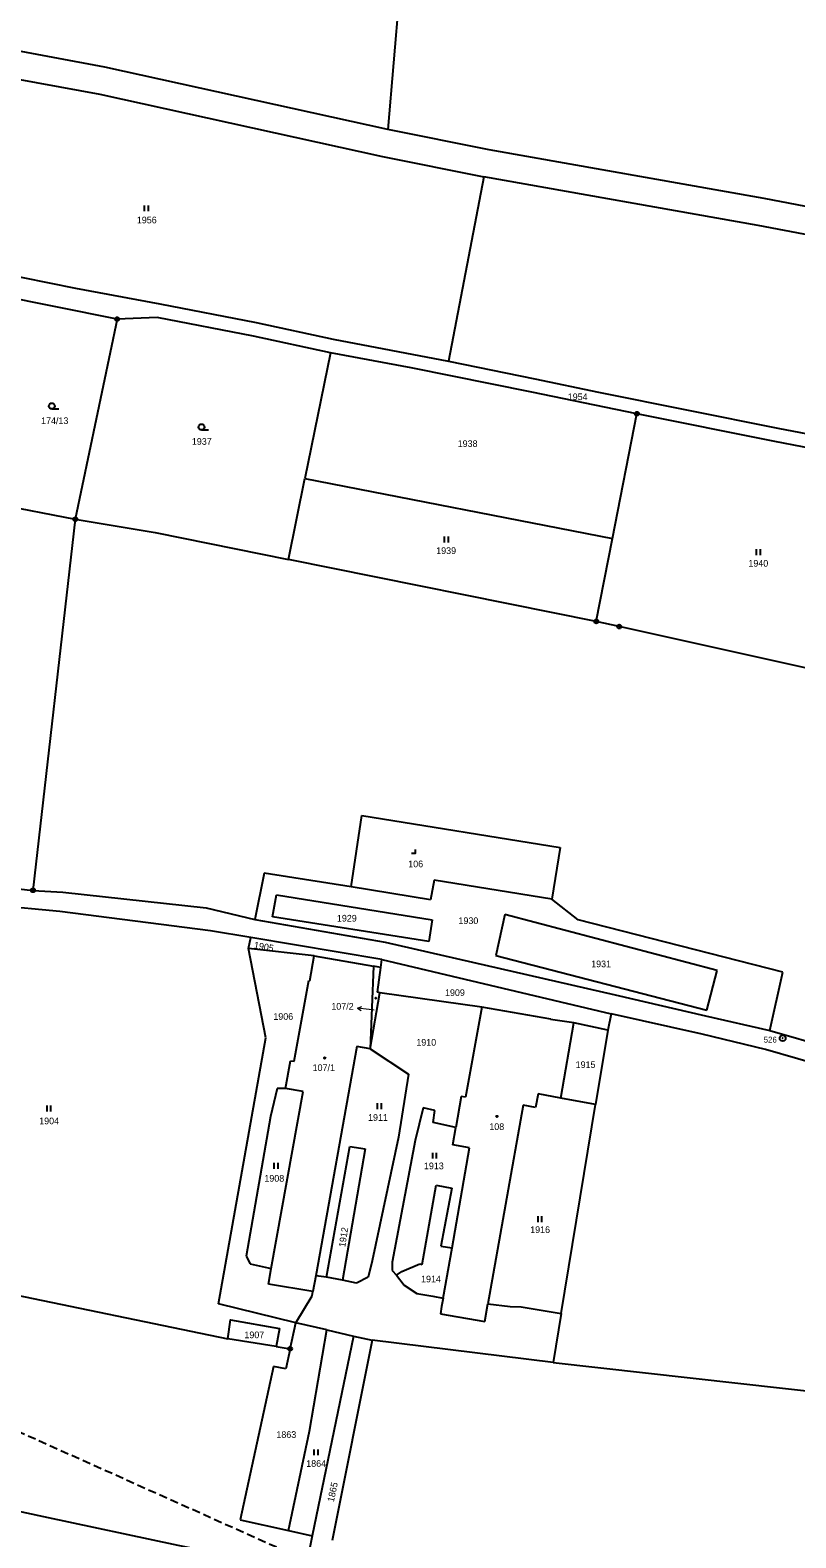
# Model space of a CAD drawing. Extents: x -601131 to -597152, y -1058536 to -1055911.
# Drawn here: x -599237.3 to -599042.1, y -1056861.6 to -1056477.3 of the extents above; entities that cross this region are included whole.
import ezdxf
from ezdxf.enums import TextEntityAlignment as Align

# ---------------------------------------------------------------- set-up
doc = ezdxf.new("R2010")
doc.units = 0
doc.header["$LTSCALE"] = 0.68
doc.linetypes.add('MEDIUM_DASHED', pattern=[4.5, 3, -1.5])
for name, color, linetype, lineweight in [('1', 7, 'Continuous', 25), ('3', 7, 'Continuous', 25), ('5', 7, 'Continuous', 25), ('6', 7, 'Continuous', 25), ('7', 7, 'Continuous', 13), ('8', 7, 'Continuous', 25)]:
    doc.layers.add(name, color=color, linetype=linetype, lineweight=lineweight)
doc.layers.add('2', color=7, linetype='Continuous')

msp = doc.modelspace()

# ---------------------------------------------------------------- linework, layer by layer
at = {"layer": '1'}
for p, q in [((-599138.92, -1056418.42), (-599146.08, -1056502.65)), ((-599218.22, -1056486.75), (-599246.19, -1056481.54)), ((-599249.34, -1056488.19), (-599219.47, -1056493.64)), ((-599146.08, -1056502.65), (-599218.22, -1056486.75)), ((-599219.47, -1056493.64), (-599147.48, -1056509.51)), ((-599120.3, -1056507.82), (-599146.08, -1056502.65)), ((-599050.18, -1056520.28), (-599120.3, -1056507.82)), ((-599147.48, -1056509.51), (-599121.64, -1056514.69)), ((-599121.64, -1056514.69), (-599130.68, -1056561.74)), ((-599051.76, -1056527.1), (-599121.64, -1056514.69)), ((-598999.34, -1056530.04), (-599050.18, -1056520.28)), ((-599000.76, -1056536.89), (-599051.76, -1056527.1)), ((-599254.19, -1056537.36), (-599225.68, -1056543.1)), ((-599215.08, -1056551), (-599254.26, -1056543.1)), ((-599225.68, -1056543.1), (-599204.19, -1056547.14)), ((-599204.19, -1056547.14), (-599179.64, -1056551.87)), ((-599215.08, -1056551), (-599225.75, -1056602)), ((-599204.88, -1056550.57), (-599215.08, -1056551)), ((-599180.34, -1056555.3), (-599204.88, -1056550.57)), ((-599179.64, -1056551.87), (-599160.02, -1056556.11)), ((-599160.69, -1056559.55), (-599180.34, -1056555.3)), ((-599160.02, -1056556.11), (-599130.68, -1056561.74)), ((-599160.69, -1056559.55), (-599167.22, -1056591.58)), ((-599140.17, -1056563.39), (-599160.69, -1056559.55)), ((-599130.68, -1056561.74), (-599108.66, -1056566.19)), ((-599109.4, -1056569.61), (-599140.17, -1056563.39)), ((-599108.66, -1056566.19), (-599092.43, -1056569.59)), ((-599082.63, -1056575.11), (-599109.4, -1056569.61)), ((-599092.43, -1056569.59), (-599046.74, -1056578.78)), ((-599088.85, -1056606.91), (-599082.63, -1056575.11)), ((-599047.5, -1056582.19), (-599082.63, -1056575.11)), ((-599046.74, -1056578.78), (-599000.52, -1056587.59)), ((-599001.09, -1056591.04), (-599047.5, -1056582.19)), ((-599171.43, -1056612.23), (-599167.22, -1056591.58)), ((-599167.22, -1056591.58), (-599088.85, -1056606.91)), ((-599265.11, -1056594.43), (-599225.75, -1056602)), ((-599225.75, -1056602), (-599236.54, -1056696.59)), ((-599225.75, -1056602), (-599205.44, -1056605.38)), ((-599205.44, -1056605.38), (-599171.43, -1056612.23)), ((-599092.98, -1056628.05), (-599088.85, -1056606.91)), ((-599092.98, -1056628.05), (-599171.43, -1056612.23)), ((-599087.13, -1056629.35), (-599092.98, -1056628.05)), ((-599039.03, -1056640.06), (-599087.13, -1056629.35)), ((-599155.42, -1056695.72), (-599152.74, -1056677.55)), ((-599152.74, -1056677.55), (-599102.17, -1056685.67)), ((-599102.17, -1056685.67), (-599104.32, -1056698.83)), ((-599177.64, -1056692.2), (-599179.99, -1056704.03)), ((-599155.42, -1056695.72), (-599177.64, -1056692.2)), ((-599257.46, -1056694.29), (-599236.54, -1056696.59)), ((-599135.22, -1056698.99), (-599155.42, -1056695.72)), ((-599134.28, -1056694.02), (-599135.22, -1056698.99)), ((-599104.32, -1056698.83), (-599134.28, -1056694.02)), ((-599229.72, -1056702.02), (-599261.35, -1056698.89)), ((-599236.54, -1056696.59), (-599228.94, -1056697.02)), ((-599228.94, -1056697.02), (-599192.37, -1056701.08)), ((-599175.52, -1056703.3), (-599174.47, -1056697.69)), ((-599174.47, -1056697.69), (-599134.79, -1056704.07)), ((-599097.57, -1056704.11), (-599104.32, -1056698.83)), ((-599191.33, -1056706.93), (-599229.72, -1056702.02)), ((-599192.37, -1056701.08), (-599179.99, -1056704.03)), ((-599135.66, -1056709.64), (-599175.52, -1056703.3)), ((-599116.27, -1056702.75), (-599118.62, -1056713.23)), ((-599062.17, -1056716.98), (-599116.27, -1056702.75)), ((-599181.05, -1056708.63), (-599191.33, -1056706.93)), ((-599179.99, -1056704.03), (-599146.83, -1056709.8)), ((-599134.79, -1056704.07), (-599135.66, -1056709.64)), ((-599045.45, -1056717.46), (-599097.57, -1056704.11)), ((-599181.64, -1056711.41), (-599181.05, -1056708.63)), ((-599164.91, -1056713.29), (-599181.64, -1056711.41)), ((-599177.22, -1056734.19), (-599181.64, -1056711.41)), ((-599147.65, -1056714.22), (-599181.05, -1056708.63)), ((-599146.83, -1056709.8), (-599088.14, -1056723.22)), ((-599165.97, -1056719.61), (-599164.91, -1056713.29)), ((-599164.91, -1056713.29), (-599149.77, -1056715.9)), ((-599147.86, -1056716.23), (-599147.65, -1056714.22)), ((-599147.65, -1056714.22), (-599089.21, -1056728.1)), ((-599118.62, -1056713.23), (-599064.81, -1056727.13)), ((-599149.77, -1056715.9), (-599150.65, -1056736.94)), ((-599147.86, -1056716.23), (-599149.77, -1056715.9)), ((-599148.73, -1056722.58), (-599147.86, -1056716.23)), ((-599064.81, -1056727.13), (-599062.17, -1056716.98)), ((-599048.72, -1056732.31), (-599045.45, -1056717.46)), ((-599169.99, -1056740.15), (-599166.23, -1056719.58)), ((-599166.23, -1056719.58), (-599165.97, -1056719.61)), ((-599150.65, -1056736.94), (-599148.12, -1056722.73)), ((-599148.12, -1056722.73), (-599148.73, -1056722.58)), ((-599122.18, -1056726.39), (-599148.12, -1056722.73)), ((-599122.18, -1056726.39), (-599126.28, -1056749.34)), ((-599104.59, -1056729.38), (-599122.18, -1056726.39)), ((-599088.14, -1056723.22), (-599065.18, -1056728.58)), ((-599104.63, -1056729.5), (-599104.59, -1056729.38)), ((-599098.69, -1056730.39), (-599104.63, -1056729.5)), ((-599102.04, -1056749.55), (-599098.69, -1056730.39)), ((-599090.02, -1056732.25), (-599098.69, -1056730.39)), ((-599089.21, -1056728.1), (-599090.02, -1056732.25)), ((-599066.02, -1056733.24), (-599089.21, -1056728.1)), ((-599065.18, -1056728.58), (-599048.72, -1056732.31)), ((-599189.28, -1056801.96), (-599177.22, -1056734.19)), ((-599090.02, -1056732.25), (-599093.15, -1056751.21)), ((-599049.89, -1056737.17), (-599066.02, -1056733.24)), ((-599048.72, -1056732.31), (-599011.59, -1056742.97)), ((-599154.04, -1056736.41), (-599164.49, -1056794.86)), ((-599150.65, -1056736.94), (-599154.04, -1056736.41)), ((-599150.65, -1056736.94), (-599140.87, -1056743.46)), ((-599012.96, -1056747.77), (-599049.89, -1056737.17)), ((-599172.18, -1056747.08), (-599170.92, -1056740.04)), ((-599170.92, -1056740.04), (-599169.99, -1056740.15)), ((-599140.87, -1056743.46), (-599143.41, -1056759.46)), ((-599174.33, -1056747.05), (-599175.97, -1056754.24)), ((-599175.82, -1056792.93), (-599167.72, -1056747.89)), ((-599172.18, -1056747.08), (-599174.33, -1056747.05)), ((-599167.72, -1056747.89), (-599172.18, -1056747.08)), ((-599127.43, -1056749.17), (-599128.81, -1056757.02)), ((-599126.28, -1056749.34), (-599127.43, -1056749.17)), ((-599107.83, -1056748.49), (-599108.45, -1056751.91)), ((-599102.04, -1056749.55), (-599107.83, -1056748.49)), ((-599093.15, -1056751.21), (-599102.04, -1056749.55)), ((-599137.14, -1056752.04), (-599139.17, -1056760.36)), ((-599134.12, -1056752.73), (-599137.14, -1056752.04)), ((-599134.56, -1056755.73), (-599134.12, -1056752.73)), ((-599111.64, -1056751.38), (-599120.61, -1056801.94)), ((-599108.45, -1056751.91), (-599111.64, -1056751.38)), ((-599101.95, -1056804.44), (-599093.15, -1056751.21)), ((-599175.97, -1056754.24), (-599182.25, -1056789.79)), ((-599128.81, -1056757.02), (-599134.56, -1056755.73)), ((-599129.58, -1056761.41), (-599128.81, -1056757.02)), ((-599143.41, -1056759.46), (-599150.12, -1056790.98)), ((-599139.17, -1056760.36), (-599145.03, -1056791.37)), ((-599125.26, -1056762.22), (-599129.58, -1056761.41)), ((-599161.71, -1056795.16), (-599155.82, -1056761.88)), ((-599151.87, -1056762.51), (-599157.68, -1056795.91)), ((-599155.82, -1056761.88), (-599151.87, -1056762.51)), ((-599129.75, -1056787.69), (-599125.26, -1056762.22)), ((-599137.36, -1056791.91), (-599133.78, -1056771.74)), ((-599133.78, -1056771.74), (-599129.84, -1056772.46)), ((-599129.84, -1056772.46), (-599132.6, -1056787.28)), ((-599132.6, -1056787.28), (-599129.75, -1056787.69)), ((-599132.01, -1056800.51), (-599129.75, -1056787.69)), ((-599289.36, -1056789.62), (-599186.88, -1056810.87)), ((-599182.25, -1056789.79), (-599181.15, -1056791.8)), ((-599181.15, -1056791.8), (-599175.82, -1056792.93)), ((-599150.12, -1056790.98), (-599151.08, -1056795.18)), ((-599145.03, -1056791.37), (-599145.01, -1056793.47)), ((-599142.57, -1056793.75), (-599137.95, -1056791.8)), ((-599137.95, -1056791.8), (-599137.36, -1056791.91)), ((-599176.55, -1056796.94), (-599175.82, -1056792.93)), ((-599164.49, -1056794.86), (-599165.21, -1056798.87)), ((-599161.71, -1056795.16), (-599164.49, -1056794.86)), ((-599157.68, -1056795.91), (-599161.71, -1056795.16)), ((-599154.07, -1056796.68), (-599157.68, -1056795.91)), ((-599151.08, -1056795.18), (-599154.07, -1056796.68)), ((-599145.01, -1056793.47), (-599143.93, -1056794.63)), ((-599143.93, -1056794.63), (-599142.57, -1056793.75)), ((-599143.93, -1056794.63), (-599141.97, -1056797.21)), ((-599165.21, -1056798.87), (-599176.55, -1056796.94)), ((-599169.54, -1056806.85), (-599165.39, -1056799.96)), ((-599165.39, -1056799.96), (-599165.21, -1056798.87)), ((-599141.97, -1056797.21), (-599138.73, -1056799.35)), ((-599138.73, -1056799.35), (-599134.62, -1056800.05)), ((-599169.54, -1056806.85), (-599189.28, -1056801.96)), ((-599134.62, -1056800.05), (-599132.01, -1056800.51)), ((-599132.39, -1056802.68), (-599132.72, -1056804.55)), ((-599132.01, -1056800.51), (-599132.39, -1056802.68)), ((-599121.41, -1056806.45), (-599120.61, -1056801.94)), ((-599120.61, -1056801.94), (-599114.91, -1056802.66)), ((-599114.91, -1056802.66), (-599112.1, -1056802.76)), ((-599112.1, -1056802.76), (-599101.95, -1056804.44)), ((-599171.01, -1056813.42), (-599169.54, -1056806.85)), ((-599161.69, -1056808.64), (-599169.54, -1056806.85)), ((-599132.72, -1056804.55), (-599121.41, -1056806.45)), ((-599101.95, -1056804.44), (-599104.01, -1056816.89)), ((-599174.53, -1056812.86), (-599186.88, -1056810.87)), ((-599173.72, -1056808.24), (-599174.53, -1056812.86)), ((-599166.08, -1056834.46), (-599161.69, -1056808.64)), ((-599154.89, -1056810.19), (-599165.35, -1056861.13)), ((-599161.69, -1056808.64), (-599154.89, -1056810.19)), ((-599150.14, -1056811.27), (-599160.28, -1056862.26)), ((-599154.89, -1056810.19), (-599150.14, -1056811.27)), ((-599104.01, -1056816.89), (-599150.14, -1056811.27)), ((-599174.53, -1056812.86), (-599171.01, -1056813.42)), ((-599171.01, -1056813.42), (-599172.14, -1056818.5)), ((-599175.28, -1056817.96), (-599183.76, -1056857.04)), ((-599172.14, -1056818.5), (-599175.28, -1056817.96)), ((-599104.01, -1056816.89), (-598929.16, -1056836.6)), ((-599171.43, -1056859.78), (-599166.08, -1056834.46)), ((-599233.79, -1056856.28), (-599243.65, -1056854.14)), ((-599183.76, -1056857.04), (-599171.43, -1056859.78)), ((-599171.43, -1056859.78), (-599165.35, -1056861.13)), ((-599165.35, -1056861.13), (-599167.19, -1056870.09))]:
    msp.add_line(p, q, dxfattribs=at)
for points in [[(-599186.88, -1056810.87), (-599186.2, -1056806.05), (-599173.72, -1056808.24)], [(-599178.14, -1056867.87), (-599199.51, -1056863.54), (-599233.79, -1056856.28)]]:
    msp.add_lwpolyline(points, dxfattribs=at)
at = {"layer": '3'}
for p, q in [((-599208.131, -1056523.5), (-599208.131, -1056522)), ((-599207.13, -1056523.5), (-599207.13, -1056522)), ((-599231.723, -1056573.89), (-599229.973, -1056573.89)), ((-599193.593, -1056579.25), (-599191.843, -1056579.25)), ((-599131.681, -1056607.89), (-599131.681, -1056606.39)), ((-599130.68, -1056607.89), (-599130.68, -1056606.39)), ((-599052.161, -1056611.17), (-599052.161, -1056609.67)), ((-599051.16, -1056611.17), (-599051.16, -1056609.67)), ((-599232.951, -1056752.92), (-599232.951, -1056751.42)), ((-599231.95, -1056752.92), (-599231.95, -1056751.42)), ((-599148.751, -1056752.35), (-599148.751, -1056750.85)), ((-599147.75, -1056752.35), (-599147.75, -1056750.85)), ((-599134.671, -1056764.97), (-599134.671, -1056763.47)), ((-599133.67, -1056764.97), (-599133.67, -1056763.47)), ((-599175.041, -1056767.56), (-599175.041, -1056766.06)), ((-599174.04, -1056767.56), (-599174.04, -1056766.06)), ((-599107.831, -1056781.12), (-599107.831, -1056779.62)), ((-599106.83, -1056781.12), (-599106.83, -1056779.62)), ((-599164.891, -1056840.58), (-599164.891, -1056839.08)), ((-599163.89, -1056840.58), (-599163.89, -1056839.08))]:
    msp.add_line(p, q, dxfattribs=at)
msp.add_lwpolyline([(-599140.051, -1056687.15), (-599139.05, -1056687.15), (-599139.05, -1056686.15)], dxfattribs=at)
for centre in [(-599231.7229, -1056573.1398), (-599193.5929, -1056578.4998)]:
    msp.add_circle(centre, 0.75, dxfattribs=at)
at = {"layer": '5'}
for centre in [(-599149.1668, -1056724.0692), (-599162.1768, -1056739.3192), (-599118.3168, -1056754.2092)]:
    msp.add_circle(centre, 0.175, dxfattribs=at)
at = {"layer": '6', "linetype": 'MEDIUM_DASHED'}
msp.add_line((-599168.92, -1056866.53), (-599311.59, -1056802.59), dxfattribs=at)
at = {"layer": '7'}
msp.add_line((-599153.819, -1056726.574), (-599152.886, -1056727.193), dxfattribs=at)
msp.add_lwpolyline([(-599149.6, -1056727.09), (-599150.84, -1056726.94), (-599153.819, -1056726.574), (-599152.764, -1056726.199)], dxfattribs=at)
at = {"layer": '8'}
for centre, radius in [((-599215.08, -1056550.9999), 0.5), ((-599215.08, -1056550.9999), 0.0303), ((-599082.63, -1056575.1099), 0.5), ((-599082.63, -1056575.1099), 0.0303), ((-599225.75, -1056601.9999), 0.5), ((-599225.75, -1056601.9999), 0.0303), ((-599092.98, -1056628.0499), 0.5), ((-599092.98, -1056628.0499), 0.0303), ((-599087.13, -1056629.3499), 0.5), ((-599087.13, -1056629.3499), 0.0303), ((-599236.54, -1056696.5899), 0.5), ((-599236.54, -1056696.5899), 0.0303), ((-599045.48, -1056734.2698), 0.75), ((-599045.48, -1056734.2698), 0.03), ((-599171.01, -1056813.4199), 0.5), ((-599171.01, -1056813.4199), 0.0303)]:
    msp.add_circle(centre, radius, dxfattribs=at)

# ---------------------------------------------------------------- texts
at = {"layer": '2'}
for s, p in [('1956', (-599207.54, -1056526.582)), ('1954', (-599097.73, -1056571.642)), ('1937', (-599193.52, -1056583.022)), ('1938', (-599125.78, -1056583.582)), ('1939', (-599131.25, -1056610.852)), ('1940', (-599051.69, -1056614.082)), ('106', (-599139.009, -1056690.702)), ('1929', (-599156.56, -1056704.542)), ('1930', (-599125.58, -1056705.172)), ('1931', (-599091.76, -1056716.182)), ('1909', (-599129.01, -1056723.502)), ('1906', (-599172.76, -1056729.592)), ('1910', (-599136.32, -1056736.172)), ('107/1', (-599162.43, -1056742.652)), ('1915', (-599095.72, -1056741.862)), ('1911', (-599148.62, -1056755.332)), ('1904', (-599232.43, -1056756.202)), ('108', (-599118.349, -1056757.662)), ('1908', (-599175.04, -1056770.842)), ('1913', (-599134.38, -1056767.662)), ('1916', (-599107.3, -1056783.932)), ('1914', (-599135.11, -1056796.502)), ('1907', (-599180.13, -1056810.732)), ('1863', (-599171.98, -1056836.142)), ('1864', (-599164.37, -1056843.522))]:
    msp.add_text(s, height=1.7, dxfattribs=at).set_placement(p, align=Align.CENTER)
msp.add_text('174/13', height=1.7, dxfattribs=at).set_placement((-599234.47, -1056577.745))
for s, rotation, p in [('1905', 350, (-599177.8366, -1056711.7761)), ('1912', 81, (-599156.5818, -1056785.122)), ('1865', 78, (-599159.3556, -1056850.1157))]:
    msp.add_text(s, height=1.7, rotation=rotation, dxfattribs=at).set_placement(p, align=Align.CENTER)
msp.add_text('107/2', height=1.7, dxfattribs=at).set_placement((-599154.82, -1056727.005), align=Align.RIGHT)
at = {"layer": '8'}
msp.add_text('526', height=1.5, dxfattribs=at).set_placement((-599046.979, -1056735.387), align=Align.RIGHT)

doc.saveas('drawing.dxf')
